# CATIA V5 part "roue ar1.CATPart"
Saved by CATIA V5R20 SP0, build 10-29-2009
Part number: roue ar1
Bounding box of the stored display mesh (mm): x -275 to -225, y 180 to 260, z 0.01 to 79.99
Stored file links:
  D:\Dropbox\Pack 1 sylvain\mmoreau\mmoreau\mmoreau\fin\roue ar1.CATPart
  U:\think motion\fin\think motion2.CATProduct
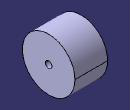
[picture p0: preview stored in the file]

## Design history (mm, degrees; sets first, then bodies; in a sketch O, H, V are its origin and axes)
Set1
  Plane1: linked copy from another document
  Point1: linked copy from another document
Body1 (main body)
  Sketch1 on Plane1, origin (-225, 0, 0), H (0, 1, 0), V (0, 0, 1)
    circle A1 centre (220, 40) radius 40
    point P1 (220, 40)
    reference projected point E1 (220, 40) from Point1
    circle A2 centre (220, 40) radius 5
    point P2 (220, 40)
    reference projected point E2 (220, 40) from Point1
    radius A2 = 5
    coincidence: P1 E1, P2 E2
    tangency: A1 H
  Pad1: profile Sketch1, direction (-1, 0, 0), length 50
